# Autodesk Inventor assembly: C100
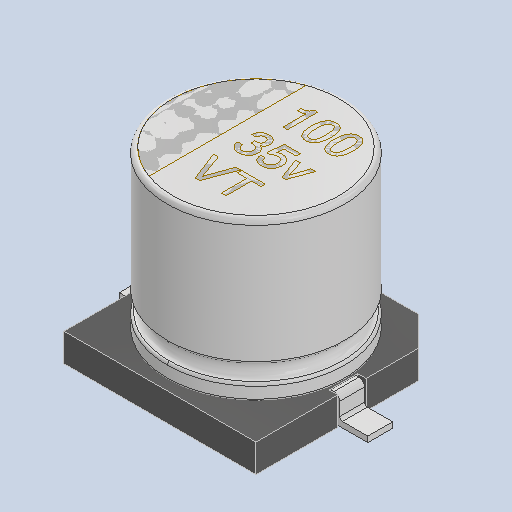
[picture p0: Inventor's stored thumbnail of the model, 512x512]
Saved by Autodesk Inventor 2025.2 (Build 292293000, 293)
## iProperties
Created: 2025-04
Part Number: C100
Description: PART--DESC
Document SubType Name: Assembly
Designer: BennF
Author: BennF
Revision Number: NONE
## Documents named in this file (4)
- C:\Users\BennF\Nextcloud\Benutzer\CNC JarBeRi\existing parts\Electronics\RepRap A4988 Shied (USE WITHOUT ARDUINO)\reprap-a4988-1.snapshot.1\RepRap\RepRap\C100.iam
- C:\Users\BennF\Nextcloud\Benutzer\CNC JarBeRi\existing parts\Electronics\RepRap A4988 Shied (USE WITHOUT ARDUINO)\reprap-a4988-1.snapshot.1\RepRap\RepRap\C100 Geometry.ipt
- C:\Users\BennF\Nextcloud\Benutzer\CNC JarBeRi\existing parts\Electronics\RepRap A4988 Shied (USE WITHOUT ARDUINO)\reprap-a4988-1.snapshot.1\RepRap\RepRap\name3.ipt
- C:\Users\BennF\Nextcloud\Benutzer\CNC JarBeRi\existing parts\Electronics\RepRap A4988 Shied (USE WITHOUT ARDUINO)\reprap-a4988-1.snapshot.1\RepRap\RepRap\bay.iam
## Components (3 placed, 3 different names)
1. C100 Geometry
2. name3
3. bay [sub-assembly]
